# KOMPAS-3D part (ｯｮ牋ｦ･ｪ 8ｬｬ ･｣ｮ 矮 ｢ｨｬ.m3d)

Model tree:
1. Эскиз:1
2. Операция выдавливания:1
     Расстояние 1 = 8
3. Эскиз:2
4. Операция выдавливания:2
     Расстояние 1 = 1
5. Эскиз:3
6. Операция выдавливания:3
     Расстояние 1 = 2.5; Угол 1 = 8
7. Эскиз:4
8. Вырезать элемент выдавливания:1
     Расстояние 1 = 20
9. Эскиз:5
10. Вырезать элемент выдавливания:2
     Расстояние 1 = 3; Угол 1 = 19
11. Скругление:1
     Радиус = 1
12. Скругление:2
     Радиус = 1
13. Скругление:3
     Радиус = 1
14. Эскиз:6
15. Эскиз:7
16. Вырезать элемент выдавливания:3
     Расстояние 2 = 30; Расстояние 1 = 60
17. Эскиз:8
18. Вырезать элемент выдавливания:4
     Расстояние 2 = 30; Расстояние 1 = 60
19. Эскиз:9
20. Операция выдавливания:4
     Расстояние 1 = 10; Расстояние 2 = 62
21. Эскиз:10
22. Вырезать элемент выдавливания:5
     Расстояние 2 = 30; Расстояние 1 = 60
23. Скругление:4
     Радиус = 2
24. Скругление:5
     Радиус = 2
25. Эскиз:11
26. Вырезать элемент выдавливания:6
     Расстояние 1 = 10
27. Эскиз:12
28. Вырезать элемент выдавливания:7
     Расстояние 1 = 2.5
29. Эскиз:13
30. Вырезать элемент выдавливания:8
     Расстояние 2 = 40; Расстояние 1 = 30
31. Эскиз:14
32. Операция выдавливания:5
     Расстояние 1 = 10
33. Операция выдавливания:6
     Расстояние 1 = 2.5; Расстояние 2 = 5.94316
34. Эскиз:15
35. Вырезать элемент выдавливания:9
     Расстояние 1 = 20
36. Скругление:6
     Радиус = 1
37. Скругление:7
     Радиус = 1
